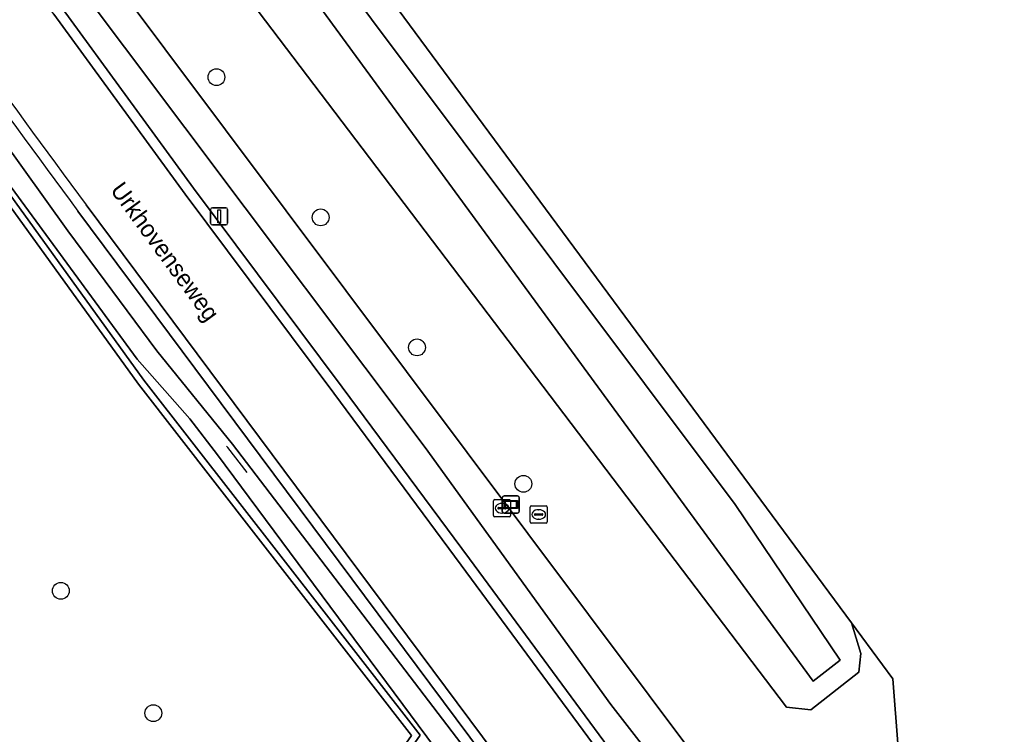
# Model space of a CAD drawing. Extents: x 164494 to 166241, y 382475 to 384495.
# Drawn here: x 164864.1 to 164921.5, y 383377.8 to 383419.5 of the extents above; entities that cross this region are included whole.
import ezdxf

# ---------------------------------------------------------------- set-up
doc = ezdxf.new("R2010")
doc.units = 0
for name, color, linetype in [('IMGEO_Berm_halfverhard', 7, 'Continuous'), ('IMGEO_Boom', 7, 'Continuous'), ('IMGEO_Bouwland', 7, 'Continuous'), ('IMGEO_Brandkraan', 7, 'Continuous'), ('IMGEO_Duiker', 7, 'Continuous'), ('IMGEO_Erf', 7, 'Continuous'), ('IMGEO_Grasland_overig', 7, 'Continuous'), ('IMGEO_Groenvoorziening', 7, 'Continuous'), ('IMGEO_Haag', 7, 'Continuous'), ('IMGEO_Lichtmast', 7, 'Continuous'), ('IMGEO_Oever', 7, 'Continuous'), ('IMGEO_Openbare_ruimte_label', 7, 'Continuous'), ('IMGEO_Rijbaan_lokaal_gesloten', 7, 'Continuous'), ('IMGEO_Rioolput', 7, 'Continuous'), ('IMGEO_Verklikker', 7, 'Continuous'), ('IMGEO_Waterloop', 7, 'Continuous')]:
    doc.layers.add(name, color=color, linetype=linetype)

msp = doc.modelspace()

# ---------------------------------------------------------------- linework, layer by layer
at = {"layer": 'IMGEO_Berm_halfverhard'}
for points in [[(164866.112, 383419.793), (164873.759, 383409.297), (164882.427, 383397.698), (164889.835, 383387.688), (164899.015, 383375.227), (164904.989, 383367.182), (164910.131, 383360.313), (164917.166, 383350.925), (164917.265, 383350.994), (164917.658, 383351.268), (164910.612, 383360.672), (164905.471, 383367.54), (164899.498, 383375.583), (164890.317, 383388.044), (164882.908, 383398.057), (164874.244, 383409.65), (164866.601, 383420.14)], [(164867.512, 383408.316), (164897.147, 383368.52), (164898.891, 383366.181), (164946.531, 383302.21), (164947.016, 383302.564), (164899.311, 383366.621), (164897.533, 383369.007), (164867.994, 383408.673)]]:
    msp.add_lwpolyline(points, dxfattribs=at)
for centre, radius, start, end in [((165414.739, 383813.768), 680.465, 212.479032, 216.535564), ((165413.22, 383812.709), 679.214, 212.469189, 216.540029)]:
    msp.add_arc(centre, radius, start, end, dxfattribs=at)
at = {"layer": 'IMGEO_Boom'}
for centre in [(164875.58, 383416.118), (164881.651, 383407.946), (164887.263, 383400.373), (164893.458, 383392.423), (164866.516, 383386.186), (164871.907, 383379.064)]:
    msp.add_circle(centre, 0.489, dxfattribs=at)
at = {"layer": 'IMGEO_Bouwland'}
msp.add_lwpolyline([(164939.064, 383467.989), (164938.58, 383467.935), (164933.685, 383466.564), (164926.474, 383465.463), (164910.854, 383460.501), (164868.575, 383444.955), (164868.931, 383444.423), (164876.262, 383433.486), (164912.566, 383384.323), (164914.978, 383381.056), (164915.281, 383377.04), (164913.179, 383375.78), (164908.171, 383370.539), (164912.922, 383363.364), (164915.309, 383360.31), (164919.551, 383354.884)], dxfattribs=at)
at = {"layer": 'IMGEO_Brandkraan'}
for p, q in [((164891.788, 383391.502), (164892.64, 383391.502)), ((164891.713, 383390.576), (164891.713, 383391.428)), ((164891.972, 383390.996), (164891.972, 383391.008)), ((164892.41, 383390.959), (164892.012, 383390.959)), ((164892.015, 383391.045), (164892.413, 383391.045)), ((164892.201, 383391.282), (164892.226, 383391.282)), ((164892.456, 383391.008), (164892.456, 383390.996)), ((164892.714, 383391.428), (164892.714, 383390.576)), ((164892.64, 383390.502), (164891.788, 383390.502)), ((164892.224, 383390.722), (164892.199, 383390.722))]:
    msp.add_line(p, q, dxfattribs=at)
for points in [[(164891.788, 383391.502), (164892.64, 383391.502)], [(164891.713, 383390.576), (164891.713, 383391.428)], [(164892.714, 383391.428), (164892.714, 383390.576)], [(164892.64, 383390.502), (164891.788, 383390.502)]]:
    msp.add_lwpolyline(points, dxfattribs=at)
for centre, radius, start, end in [((164891.79, 383391.426), 0.0765, 91.55205, 178.44795), ((164891.79, 383391.426), 0.0765, 91.55205, 178.44795), ((164892.638, 383391.426), 0.0765, 1.55205, 88.44795), ((164892.638, 383391.426), 0.0765, 1.55205, 88.44795), ((164892.012, 383391.005), 0.0403, 85.87752, 175.75265), ((164892.009, 383390.995), 0.0366, 178.93798, 274.71019), ((164892.413, 383391.002), 0.043, 264.86636, 352.45326), ((164892.417, 383391.007), 0.0386, 1.73085, 96.63898), ((164891.79, 383390.578), 0.0765, 181.55205, 268.44795), ((164891.79, 383390.578), 0.0765, 181.55205, 268.44795), ((164892.638, 383390.578), 0.0765, 271.55205, 358.44795), ((164892.638, 383390.578), 0.0765, 271.55205, 358.44795)]:
    msp.add_arc(centre, radius, start, end, dxfattribs=at)
for centre, major_axis, ratio, start_param, end_param in [((164892.2, 383391.002), (-0.387, 0.002), 0.722429, 4.712389, 7.853982), ((164892.225, 383391.002), (-0.39, 0.002), 0.717154, 1.570796, 4.712389)]:
    msp.add_ellipse(centre, major_axis=major_axis, ratio=ratio, start_param=start_param, end_param=end_param, dxfattribs=at)
at = {"layer": 'IMGEO_Duiker'}
msp.add_lwpolyline([(164877.368, 383393.078), (164876.238, 383394.531), (164876.165, 383394.625)], dxfattribs=at)
at = {"layer": 'IMGEO_Erf'}
msp.add_lwpolyline([(164785.335, 383462.011), (164820.036, 383413.911), (164867.478, 383349.751), (164886.943, 383377.76), (164871.034, 383398.226), (164846.57, 383432.139), (164840.127, 383441.874), (164838.209, 383445.412), (164832.004, 383456.853), (164825.553, 383468.751), (164821.992, 383475.908), (164820.222, 383475.231)], dxfattribs=at)
at = {"layer": 'IMGEO_Grasland_overig'}
for points in [[(164846.632, 383449.047), (164846.701, 383448.936), (164847.079, 383449.156), (164849.084, 383445.806), (164853.899, 383438.366), (164858.738, 383431.203), (164866.601, 383420.14), (164874.244, 383409.65), (164882.908, 383398.057), (164890.317, 383388.044), (164899.498, 383375.583), (164905.471, 383367.54), (164910.612, 383360.672), (164917.658, 383351.268), (164920.321, 383353.128)], [(164854.9, 383441.379), (164907.844, 383370.661), (164907.934, 383370.559), (164908.171, 383370.539), (164913.179, 383375.78), (164915.281, 383377.04), (164914.978, 383381.056), (164912.566, 383384.323), (164913.106, 383382.53), (164913.003, 383381.452), (164910.203, 383379.262), (164908.784, 383379.416), (164877.214, 383421.031), (164863.009, 383441.79)], [(164912.922, 383363.364), (164908.171, 383370.539), (164907.934, 383370.559), (164906.448, 383369.416), (164898.556, 383379.568), (164887.73, 383394.536), (164859.723, 383431.842)]]:
    msp.add_lwpolyline(points, dxfattribs=at)
at = {"layer": 'IMGEO_Groenvoorziening'}
for points in [[(164888.281, 383377.086), (164875.652, 383394.111), (164874.038, 383396.206), (164870.973, 383399.679), (164852.177, 383425.35), (164846.184, 383433.778), (164844.42, 383436.392), (164840.671, 383441.945), (164839.448, 383444.057), (164839.409, 383444.039), (164840.471, 383442.08), (164846.9, 383432.367), (164871.354, 383398.466), (164887.439, 383377.774), (164867.735, 383349.418), (164868.899, 383347.969), (164887.778, 383374.96)], [(164847.394, 383434.456), (164866.917, 383407.172), (164872.113, 383400.175), (164876.524, 383394.735), (164895.264, 383370.164)], [(164846.57, 383432.139), (164871.034, 383398.226), (164886.943, 383377.76), (164867.478, 383349.751), (164867.604, 383349.581), (164867.735, 383349.418), (164887.439, 383377.774), (164871.354, 383398.466), (164846.9, 383432.367)], [(164897.147, 383368.52), (164867.512, 383408.316)]]:
    msp.add_lwpolyline(points, dxfattribs=at)
msp.add_arc((165413.22, 383812.709), 679.214, 212.469189, 216.540029, dxfattribs=at)
at = {"layer": 'IMGEO_Haag'}
msp.add_lwpolyline([(164846.57, 383432.139), (164871.034, 383398.226), (164886.943, 383377.76), (164867.478, 383349.751), (164867.604, 383349.581), (164867.735, 383349.418), (164887.439, 383377.774), (164871.354, 383398.466), (164846.9, 383432.367)], dxfattribs=at)
at = {"layer": 'IMGEO_Lichtmast'}
for p, q in [((164875.245, 383407.611), (164875.245, 383408.411)), ((164875.245, 383408.411), (164875.245, 383407.611)), ((164875.345, 383408.511), (164876.135, 383408.511)), ((164876.135, 383408.511), (164875.345, 383408.511)), ((164876.235, 383408.411), (164876.235, 383407.611)), ((164876.235, 383407.611), (164876.235, 383408.411)), ((164876.135, 383407.511), (164875.345, 383407.511)), ((164875.345, 383407.511), (164876.135, 383407.511))]:
    msp.add_line(p, q, dxfattribs=at)
msp.add_lwpolyline([(164875.665, 383408.386), (164875.815, 383408.386), (164875.815, 383407.636), (164875.665, 383407.636), (164875.665, 383408.386)], dxfattribs=at)
for centre, start, end in [((164875.345, 383408.411), 90, 180), ((164875.345, 383408.411), 90, 180), ((164876.135, 383408.411), 0, 90), ((164876.135, 383408.411), 360, 90), ((164875.345, 383407.611), 180, 270), ((164875.345, 383407.611), 180, 270), ((164876.135, 383407.611), 270, 0), ((164876.135, 383407.611), 270, 0)]:
    msp.add_arc(centre, 0.1, start, end, dxfattribs=at)
at = {"layer": 'IMGEO_Oever'}
for points in [[(164863.009, 383441.79), (164877.214, 383421.031), (164908.784, 383379.416), (164910.203, 383379.262), (164913.003, 383381.452), (164913.106, 383382.53), (164912.566, 383384.323), (164876.262, 383433.486), (164868.931, 383444.423), (164868.575, 383444.955), (164910.854, 383460.501), (164926.474, 383465.463), (164933.685, 383466.564), (164938.58, 383467.935), (164939.064, 383467.989)], [(164936.301, 383468.215), (164934.715, 383467.812), (164931.252, 383467.086), (164925.991, 383466.081), (164874.646, 383448.92), (164868.943, 383447.047), (164867.326, 383444.749), (164867.752, 383443.303), (164868.773, 383440.664), (164905.795, 383391.218), (164911.909, 383382.143), (164910.33, 383380.925), (164865.199, 383442.664), (164864.348, 383444.622)]]:
    msp.add_lwpolyline(points, dxfattribs=at)
at = {"layer": 'IMGEO_Rijbaan_lokaal_gesloten'}
for points in [[(164951.985, 383304.388), (164949.568, 383307.631), (164927.281, 383337.528), (164920.32, 383346.864), (164917.265, 383350.994), (164917.166, 383350.925), (164910.131, 383360.313), (164904.989, 383367.182), (164899.015, 383375.227), (164889.835, 383387.688), (164882.427, 383397.698), (164873.759, 383409.297), (164866.112, 383419.793), (164858.241, 383430.867), (164853.395, 383438.04), (164848.569, 383445.498), (164846.561, 383448.854), (164846.701, 383448.936), (164846.632, 383449.047)], [(164867.994, 383408.673), (164897.533, 383369.007), (164899.311, 383366.621), (164947.016, 383302.564), (164947.902, 383301.374), (164951.985, 383304.388)]]:
    msp.add_lwpolyline(points, dxfattribs=at)
msp.add_arc((165414.739, 383813.768), 680.465, 212.479032, 216.535564, dxfattribs=at)
at = {"layer": 'IMGEO_Rioolput'}
for p, q in [((164893.85, 383390.211), (164893.85, 383391.063)), ((164893.925, 383391.137), (164894.777, 383391.137)), ((164894.338, 383390.917), (164894.363, 383390.917)), ((164894.851, 383391.063), (164894.851, 383390.211)), ((164894.109, 383390.631), (164894.109, 383390.643)), ((164894.547, 383390.594), (164894.149, 383390.594)), ((164894.152, 383390.68), (164894.55, 383390.68)), ((164894.361, 383390.357), (164894.336, 383390.357)), ((164894.593, 383390.643), (164894.593, 383390.631)), ((164894.777, 383390.137), (164893.925, 383390.137))]:
    msp.add_line(p, q, dxfattribs=at)
for points in [[(164893.85, 383390.211), (164893.85, 383391.063)], [(164893.925, 383391.137), (164894.777, 383391.137)], [(164894.851, 383391.063), (164894.851, 383390.211)], [(164894.777, 383390.137), (164893.925, 383390.137)]]:
    msp.add_lwpolyline(points, dxfattribs=at)
for centre, radius, start, end in [((164893.927, 383391.061), 0.0765, 91.55205, 178.44795), ((164893.927, 383391.061), 0.0765, 91.55205, 178.44795), ((164894.775, 383391.061), 0.0765, 1.55205, 88.44795), ((164894.775, 383391.061), 0.0765, 1.55205, 88.44795), ((164894.149, 383390.64), 0.0403, 85.87752, 175.75265), ((164894.146, 383390.63), 0.0366, 178.93798, 274.71019), ((164894.55, 383390.637), 0.043, 264.86636, 352.45326), ((164894.554, 383390.642), 0.0386, 1.73085, 96.63898), ((164893.927, 383390.213), 0.0765, 181.55205, 268.44795), ((164893.927, 383390.213), 0.0765, 181.55205, 268.44795), ((164894.775, 383390.213), 0.0765, 271.55205, 358.44795), ((164894.775, 383390.213), 0.0765, 271.55205, 358.44795)]:
    msp.add_arc(centre, radius, start, end, dxfattribs=at)
for centre, major_axis, ratio, start_param, end_param in [((164894.337, 383390.637), (-0.387, 0.002), 0.722429, 4.712389, 7.853982), ((164894.362, 383390.637), (-0.39, 0.002), 0.717154, 1.570796, 4.712389)]:
    msp.add_ellipse(centre, major_axis=major_axis, ratio=ratio, start_param=start_param, end_param=end_param, dxfattribs=at)
at = {"layer": 'IMGEO_Verklikker'}
for p, q in [((164892.23, 383390.82), (164892.23, 383391.62)), ((164892.23, 383391.62), (164892.23, 383390.82)), ((164892.33, 383391.72), (164893.12, 383391.72)), ((164893.12, 383391.72), (164892.33, 383391.72)), ((164893.22, 383391.62), (164893.22, 383390.82)), ((164893.22, 383390.82), (164893.22, 383391.62)), ((164893.12, 383390.72), (164892.33, 383390.72)), ((164892.33, 383390.72), (164893.12, 383390.72))]:
    msp.add_line(p, q, dxfattribs=at)
for points in [[(164892.331, 383391.452), (164893.119, 383391.452), (164893.119, 383390.988), (164892.331, 383390.988), (164892.331, 383391.452)], [(164892.396, 383391.387), (164892.396, 383391.053), (164893.054, 383391.053), (164893.054, 383391.387), (164892.396, 383391.387)]]:
    msp.add_lwpolyline(points, dxfattribs=at)
for centre, start, end in [((164892.33, 383391.62), 90, 180), ((164892.33, 383391.62), 90, 180), ((164893.12, 383391.62), 0, 90), ((164893.12, 383391.62), 360, 90), ((164892.33, 383390.82), 180, 270), ((164892.33, 383390.82), 180, 270), ((164893.12, 383390.82), 270, 0), ((164893.12, 383390.82), 270, 0)]:
    msp.add_arc(centre, 0.1, start, end, dxfattribs=at)
at = {"layer": 'IMGEO_Waterloop'}
for points in [[(164910.33, 383380.925), (164911.909, 383382.143), (164905.795, 383391.218), (164868.773, 383440.664), (164867.752, 383443.303), (164867.326, 383444.749), (164868.943, 383447.047), (164874.646, 383448.92), (164925.991, 383466.081), (164931.252, 383467.086), (164934.715, 383467.812), (164936.301, 383468.215)], [(164864.348, 383444.622), (164865.199, 383442.664), (164910.33, 383380.925)], [(164859.723, 383431.842), (164887.73, 383394.536), (164898.556, 383379.568), (164906.448, 383369.416), (164907.934, 383370.559), (164907.844, 383370.661), (164854.9, 383441.379)], [(164872.113, 383400.175), (164866.917, 383407.172), (164847.394, 383434.456)], [(164852.177, 383425.35), (164870.973, 383399.679), (164874.038, 383396.206), (164875.652, 383394.111), (164888.281, 383377.086), (164889.179, 383375.876), (164894.078, 383369.272)], [(164895.264, 383370.164), (164876.524, 383394.735), (164872.113, 383400.175)]]:
    msp.add_lwpolyline(points, dxfattribs=at)

# ---------------------------------------------------------------- texts
at = {"layer": 'IMGEO_Openbare_ruimte_label'}
msp.add_text('Urkhovenseweg', height=1, rotation=306.17064, dxfattribs=at).set_placement((164869.364, 383409.532))

doc.saveas('drawing.dxf')
